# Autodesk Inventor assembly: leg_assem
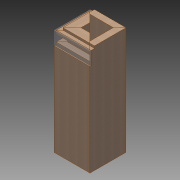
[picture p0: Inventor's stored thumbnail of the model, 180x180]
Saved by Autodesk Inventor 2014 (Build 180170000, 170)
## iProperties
Created: 2014-05
Part Number: leg_assem
Document SubType Name: Assembly
Designer: t_emanb
Author: t_emanb
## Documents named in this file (5)
- C:\Users\t_emanb\Documents\Disco Panel Table\Version 1\leg_assem.iam
- C:\Users\t_emanb\Documents\Disco Panel Table\Version 1\leg_outer.ipt
- C:\Users\t_emanb\Documents\Disco Panel Table\Version 1\leg_acrylic.ipt
- C:\Users\t_emanb\Documents\Disco Panel Table\Version 1\leg_inner.ipt
- C:\Users\t_emanb\Documents\Disco Panel Table\Version 1\leg_innerMirror.ipt
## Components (6 placed, 4 different names)
1. leg_outer:1 — Flush:1, Mate:1, Mate:2, Mate:6, Mate:7, Mate:8, Mate:14
2. leg_outer:2 — Flush:1, Mate:1, Mate:2, Mate:3, Mate:4, Mate:5, Flush:2, Mate:9, Mate:12
3. leg_acrylic:1 — Mate:6, Mate:7, Mate:8
4. leg_acrylic:2 — Mate:3, Mate:4, Mate:5
5. leg_inner:1 — Flush:2, Mate:9, Mate:12, Flush:3, Mate:13
6. leg_innerMirror:1 — Flush:3, Mate:13, Mate:14
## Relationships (15: Mate 12, Flush 3)
- Flush:1: leg_outer:1 ↔ leg_outer:2
- Mate:1: leg_outer:1 ↔ leg_outer:2
- Mate:2: leg_outer:1 ↔ leg_outer:2
- Mate:3: leg_outer:2 ↔ leg_acrylic:2
- Mate:4: leg_outer:2 ↔ leg_acrylic:2
- Mate:5: leg_outer:2 ↔ leg_acrylic:2
- Mate:6: leg_outer:1 ↔ leg_acrylic:1
- Mate:7: leg_outer:1 ↔ leg_acrylic:1
- Mate:8: leg_outer:1 ↔ leg_acrylic:1
- Flush:2: leg_outer:2 ↔ leg_inner:1
- Mate:9: leg_outer:2 ↔ leg_inner:1
- Mate:12: leg_outer:2 ↔ leg_inner:1
- Flush:3: leg_inner:1 ↔ leg_innerMirror:1
- Mate:13: leg_inner:1 ↔ leg_innerMirror:1
- Mate:14: leg_outer:1 ↔ leg_innerMirror:1
